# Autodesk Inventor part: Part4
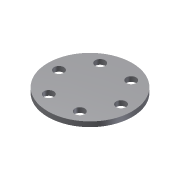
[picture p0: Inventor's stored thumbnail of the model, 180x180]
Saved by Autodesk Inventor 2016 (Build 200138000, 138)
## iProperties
Created: 2008-05
Part Number: Part4
Document SubType Name: Modeling
Designer: CADCIM
Density: 1 g/cm^3
Material: Generic
Appearance: Default
Author: CADCIM
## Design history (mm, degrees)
sketch "Sketch1"
  geometry: C1 r 17 at (0, 0)
  constraints: 1 centre point, 1 other
  dimensions: "d12" = 34 diameter of C1
extrude "Extrusion1" new body sketch "Sketch1" distance "d0" = 2; taper "d1" = 0 deg
sketch "Sketch2"
  geometry: 1 further point
hole "Hole1" sketch "Sketch2" at (5.9, 10.769) diameter "d2" = 4; stored, may be unused: countersink angle "d6" = 90 deg, drill point angle "d8" = 118 deg; dims "d3" = 6, "d4" = 4, "d5" = 2, "d7" = 8
pattern_circular "Circular Pattern1" dims angle "d10" = 360 deg
body "Solid1"
